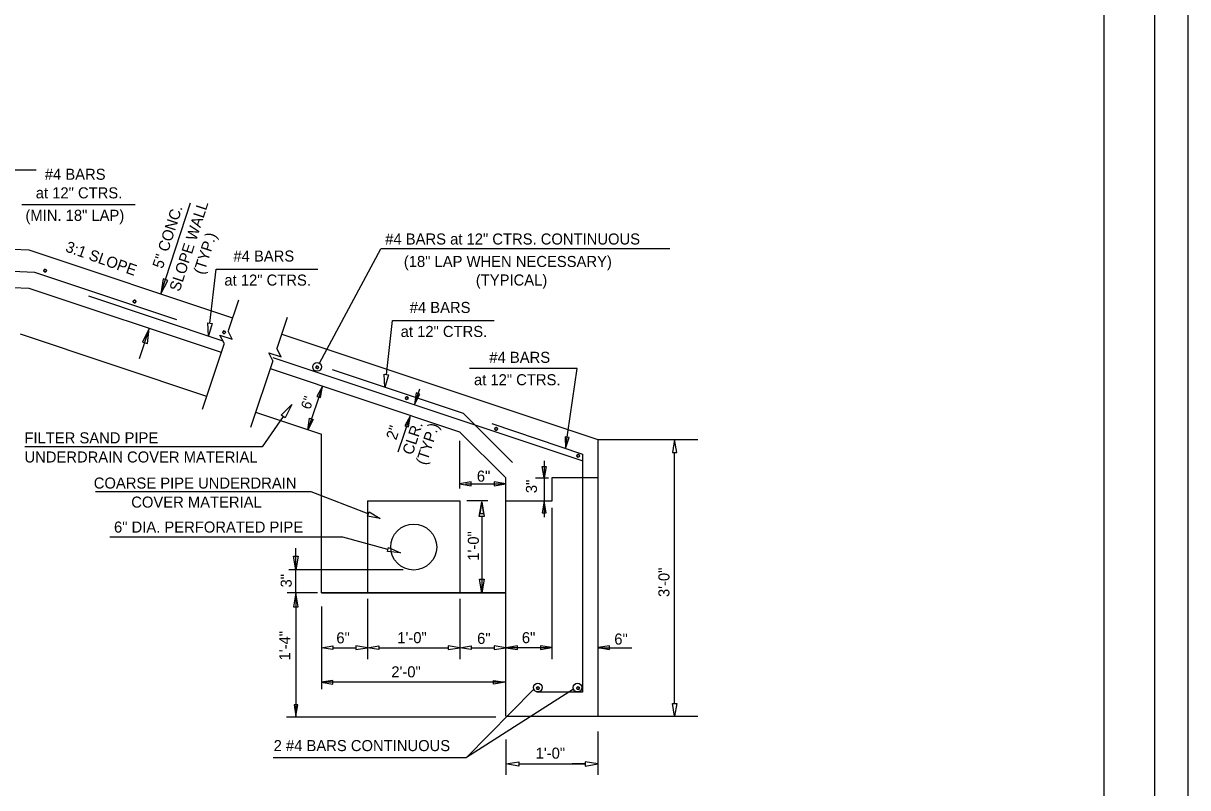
# Model space of a CAD drawing. Extents: x 570 to 2152770, y 726 to 139926.
# Drawn here: x 2151662.08 to 2151674.73, y 139329.09 to 139337.39 of the extents above; entities that cross this region are included whole.
import ezdxf

# ---------------------------------------------------------------- set-up
doc = ezdxf.new("R2010")
doc.units = 0
for name, color, linetype in [('4', 7, 'Continuous'), ('7', 7, 'Continuous'), ('9', 7, 'Continuous'), ('Default', 7, 'Continuous'), ('PR_Dimensions', 7, 'Continuous'), ('PR_Reinforcing', 7, 'Continuous'), ('PR_SlopeWall', 7, 'Continuous'), ('SHT_Plot_Shape_Full', 7, 'Continuous'), ('SHT_Plot_Shape_Half', 7, 'Continuous'), ('SHT_Sheet_Border', 7, 'Continuous'), ('T', 7, 'Continuous'), ('WEEPHOLES', 7, 'Continuous')]:
    doc.layers.add(name, color=color, linetype=linetype)

# ---------------------------------------------------------------- blocks, each defined once
blk = doc.blocks.new('DWG01008_7')
at = {"layer": 'Default'}
for p, q in [((-0.0132, 0), (0, 0.0132)), ((0, 0.0132), (0, -0.0132)), ((0, -0.0132), (0.0132, 0))]:
    blk.add_line(p, q, dxfattribs=at)
blk = doc.blocks.new('ARROWHD_15')
at = {"layer": 'Default'}
blk.add_lwpolyline([(0.0261, -0.0045), (0.0261, 0.0043), (-0.0004, -0.0001)], close=True, dxfattribs=at)

msp = doc.modelspace()

# ---------------------------------------------------------------- linework, layer by layer
at = {"layer": '4'}
for p, q in [((2151668.321, 139332.455), (2151667.821, 139332.455)), ((2151667.821, 139332.455), (2151667.821, 139332.203)), ((2151667.821, 139332.203), (2151667.321, 139332.203))]:
    msp.add_line(p, q, dxfattribs=at)
at = {"layer": '7'}
for p, q in [((2151662.047, 139334.02), (2151664.07, 139333.345)), ((2151664.603, 139333.168), (2151665.32, 139332.929)), ((2151665.32, 139331.206), (2151665.32, 139332.929)), ((2151665.32, 139331.206), (2151667.32, 139331.206))]:
    msp.add_line(p, q, dxfattribs=at)
at = {"layer": '9'}
for start, end in [(159.6694, 339.6694), (339.6694, 159.6694)]:
    msp.add_arc((2151664.26, 139334.037), 0.0143, start, end, dxfattribs=at)
at = {"layer": 'Defpoints'}
for p, q in [((2151668.321, 139332.872), (2151669.408, 139332.872)), ((2151668.321, 139329.867), (2151669.408, 139329.867))]:
    msp.add_line(p, q, dxfattribs=at)
at = {"layer": 'PR_Dimensions'}
for p, q in [((2151662.219, 139335.799), (2151660.003, 139335.799)), ((2151662.064, 139335.426), (2151663.295, 139335.426)), ((2151663.573, 139334.455), (2151663.896, 139335.442)), ((2151669.103, 139334.942), (2151665.962, 139334.942)), ((2151664.174, 139334.723), (2151665.278, 139334.723)), ((2151664.417, 139334.387), (2151664.305, 139334.051)), ((2151664.946, 139334.196), (2151664.834, 139333.86)), ((2151666.09, 139334.165), (2151667.194, 139334.165)), ((2151663.342, 139333.753), (2151663.446, 139334.07)), ((2151664.261, 139333.917), (2151664.022, 139333.2)), ((2151664.789, 139333.726), (2151664.548, 139333.002)), ((2151668.097, 139333.644), (2151666.927, 139333.644)), ((2151667.969, 139332.775), (2151668.097, 139333.644)), ((2151665.328, 139333.453), (2151665.17, 139332.978)), ((2151666.336, 139333.275), (2151666.385, 139333.423)), ((2151666.153, 139332.738), (2151666.286, 139333.134)), ((2151666.816, 139332.859), (2151666.816, 139332.34)), ((2151668.36, 139332.872), (2151669.274, 139332.872)), ((2151669.154, 139330.007), (2151669.154, 139332.732)), ((2151667.737, 139332.642), (2151667.737, 139332.203)), ((2151667.644, 139332.456), (2151667.784, 139332.456)), ((2151666.882, 139332.391), (2151667.317, 139332.391)), ((2151665.208, 139332.303), (2151662.863, 139332.303)), ((2151667.124, 139332.207), (2151666.899, 139332.207)), ((2151667.737, 139332.203), (2151667.737, 139332.028)), ((2151667.82, 139332.13), (2151667.82, 139330.487)), ((2151665.549, 139331.811), (2151663.02, 139331.811)), ((2151665.041, 139331.206), (2151665.041, 139331.692)), ((2151666.204, 139331.456), (2151664.965, 139331.456)), ((2151665.274, 139331.206), (2151664.946, 139331.206)), ((2151665.27, 139331.206), (2151664.992, 139331.206)), ((2151665.041, 139331.206), (2151665.041, 139329.868)), ((2151667.32, 139331.206), (2151665.32, 139331.206)), ((2151665.317, 139331.061), (2151665.317, 139330.162)), ((2151665.818, 139331.143), (2151665.818, 139330.486)), ((2151666.82, 139331.143), (2151666.82, 139330.486)), ((2151665.442, 139330.611), (2151665.693, 139330.611)), ((2151665.943, 139330.611), (2151666.694, 139330.611)), ((2151666.945, 139330.611), (2151667.195, 139330.611)), ((2151667.82, 139330.612), (2151667.32, 139330.612)), ((2151668.32, 139330.612), (2151668.689, 139330.612)), ((2151667.32, 139330.237), (2151665.317, 139330.237)), ((2151664.938, 139329.862), (2151667.213, 139329.862)), ((2151668.441, 139329.867), (2151669.274, 139329.867)), ((2151668.321, 139329.701), (2151668.321, 139329.23)), ((2151667.321, 139329.615), (2151667.321, 139329.23)), ((2151664.793, 139329.421), (2151666.894, 139329.421)), ((2151667.461, 139329.35), (2151668.181, 139329.35)), ((2151668.181, 139329.35), (2151668.041, 139329.35))]:
    msp.add_line(p, q, dxfattribs=at)
for points in [[(2151665.298, 139333.7), (2151665.962, 139334.942)], [(2151664.107, 139334.136), (2151664.174, 139334.723)], [(2151666.023, 139333.578), (2151666.09, 139334.165)], [(2151664.903, 139333.123), (2151664.673, 139332.794), (2151662.095, 139332.794)], [(2151665.826, 139332.064), (2151665.208, 139332.303)], [(2151667.06, 139332.036), (2151667.06, 139331.206)], [(2151666.04, 139331.679), (2151665.549, 139331.811)], [(2151668.056, 139330.16), (2151666.894, 139329.421)], [(2151667.623, 139330.159), (2151666.894, 139329.421)]]:
    msp.add_lwpolyline(points, dxfattribs=at)
for points in [[(2151664.13, 139334.133), (2151664.091, 139333.997), (2151664.084, 139334.139)], [(2151666.046, 139333.575), (2151666.007, 139333.439), (2151665.999, 139333.581)], [(2151665.269, 139333.341), (2151665.308, 139333.328), (2151665.328, 139333.453)], [(2151664.881, 139333.138), (2151664.995, 139333.254), (2151664.925, 139333.108)], [(2151665.19, 139333.103), (2151665.229, 139333.09), (2151665.17, 139332.978)], [(2151669.131, 139332.732), (2151669.178, 139332.732), (2151669.154, 139332.872)], [(2151667.716, 139332.581), (2151667.758, 139332.581), (2151667.737, 139332.456)], [(2151667.033, 139332.036), (2151667.06, 139332.196), (2151667.087, 139332.036)], [(2151667.039, 139332.071), (2151667.081, 139332.071), (2151667.06, 139332.196)], [(2151667.716, 139332.078), (2151667.758, 139332.078), (2151667.737, 139332.203)], [(2151665.835, 139332.086), (2151665.957, 139332.014), (2151665.818, 139332.042)], [(2151666.046, 139331.701), (2151666.175, 139331.642), (2151666.034, 139331.656)], [(2151665.016, 139331.606), (2151665.066, 139331.606), (2151665.041, 139331.456)], [(2151667.035, 139331.356), (2151667.085, 139331.356), (2151667.06, 139331.206)], [(2151665.016, 139331.055), (2151665.066, 139331.055), (2151665.041, 139331.206)], [(2151665.442, 139330.632), (2151665.442, 139330.591), (2151665.317, 139330.611)], [(2151665.693, 139330.632), (2151665.693, 139330.591), (2151665.818, 139330.611)], [(2151665.943, 139330.632), (2151665.943, 139330.591), (2151665.818, 139330.611)], [(2151666.694, 139330.632), (2151666.694, 139330.591), (2151666.82, 139330.611)], [(2151666.945, 139330.632), (2151666.945, 139330.591), (2151666.82, 139330.611)], [(2151667.195, 139330.632), (2151667.195, 139330.591), (2151667.32, 139330.611)], [(2151665.062, 139329.993), (2151665.02, 139329.993), (2151665.041, 139329.868)], [(2151669.131, 139330.007), (2151669.178, 139330.007), (2151669.154, 139329.867)], [(2151667.461, 139329.374), (2151667.461, 139329.327), (2151667.321, 139329.35)], [(2151668.181, 139329.374), (2151668.181, 139329.327), (2151668.321, 139329.35)]]:
    msp.add_lwpolyline(points, close=True, dxfattribs=at)
for centre in [(2151665.271, 139333.661), (2151667.668, 139330.179), (2151668.099, 139330.179)]:
    msp.add_circle(centre, 0.0479, dxfattribs=at)
at = {"layer": 'PR_Reinforcing'}
for p, q in [((2151659.233, 139334.813), (2151662.202, 139334.691)), ((2151662.202, 139334.691), (2151663.744, 139334.177)), ((2151662.787, 139334.432), (2151664.246, 139333.945)), ((2151664.789, 139333.765), (2151668.147, 139332.645)), ((2151666.862, 139333.154), (2151665.439, 139333.628)), ((2151666.862, 139333.154), (2151667.392, 139332.624)), ((2151667.168, 139333.047), (2151668.154, 139332.714)), ((2151668.154, 139332.714), (2151668.154, 139330.13)), ((2151668.154, 139330.13), (2151667.654, 139330.13))]:
    msp.add_line(p, q, dxfattribs=at)
for centre in [(2151662.317, 139334.706), (2151663.288, 139334.371), (2151664.26, 139334.036), (2151665.273, 139333.657), (2151666.244, 139333.322), (2151667.216, 139332.988), (2151668.105, 139332.696), (2151667.67, 139330.172), (2151668.105, 139330.172)]:
    msp.add_circle(centre, 0.0143, dxfattribs=at)
for centre, start, end in [((2151662.317, 139334.706), 159.6694, 339.6694), ((2151662.317, 139334.706), 339.6694, 159.6694), ((2151663.288, 139334.371), 159.6694, 339.6694), ((2151663.288, 139334.371), 339.6694, 159.6694), ((2151665.272, 139333.657), 159.6694, 339.6694), ((2151665.272, 139333.657), 339.6694, 159.6694), ((2151666.244, 139333.322), 339.6694, 159.6694), ((2151666.244, 139333.322), 159.6694, 339.6694), ((2151667.216, 139332.988), 159.6694, 339.6694), ((2151667.216, 139332.988), 339.6694, 159.6694), ((2151668.106, 139332.696), 159.6694, 339.6694), ((2151668.106, 139332.696), 339.6694, 159.6694), ((2151667.67, 139330.172), 1.9719, 181.9719), ((2151667.67, 139330.172), 181.9719, 1.9719), ((2151668.105, 139330.172), 1.9719, 181.9719), ((2151668.105, 139330.172), 181.9719, 1.9719)]:
    msp.add_arc(centre, 0.0143, start, end, dxfattribs=at)
at = {"layer": 'PR_SlopeWall'}
for p, q in [((2151659.138, 139335.058), (2151662.138, 139334.933)), ((2151659.138, 139335.058), (2151662.138, 139334.933)), ((2151662.138, 139334.933), (2151664.353, 139334.195)), ((2151659.125, 139334.641), (2151662.138, 139334.516)), ((2151659.138, 139334.641), (2151662.138, 139334.516)), ((2151662.138, 139334.516), (2151664.228, 139333.82)), ((2151662.138, 139334.516), (2151664.228, 139333.82)), ((2151664.886, 139334.017), (2151668.32, 139332.872)), ((2151664.761, 139333.642), (2151666.816, 139332.957)), ((2151666.816, 139332.957), (2151667.32, 139332.456)), ((2151668.32, 139332.872), (2151668.321, 139329.865)), ((2151667.321, 139329.867), (2151667.32, 139332.456)), ((2151667.321, 139329.867), (2151668.321, 139329.867))]:
    msp.add_line(p, q, dxfattribs=at)
at = {"layer": 'SHT_Plot_Shape_Full'}
msp.add_lwpolyline([(2151638.727, 139342.197), (2151674.727, 139342.197), (2151674.727, 139318.197), (2151638.727, 139318.197)], close=True, dxfattribs=at)
at = {"layer": 'SHT_Plot_Shape_Half'}
msp.add_lwpolyline([(2151640.365, 139341.372), (2151674.365, 139341.372), (2151674.365, 139319.372), (2151640.365, 139319.372)], close=True, dxfattribs=at)
at = {"layer": 'SHT_Sheet_Border'}
msp.add_lwpolyline([(2151673.815, 139319.872), (2151642.315, 139319.872), (2151642.315, 139340.872), (2151673.815, 139340.872)], close=True, dxfattribs=at)
at = {"layer": 'T'}
msp.add_circle((2151666.32, 139331.705), 0.25, dxfattribs=at)
at = {"layer": 'WEEPHOLES'}
for p, q in [((2151665.82, 139332.205), (2151665.82, 139331.206)), ((2151665.82, 139332.205), (2151666.82, 139332.205)), ((2151666.82, 139332.205), (2151666.82, 139331.206)), ((2151665.82, 139331.206), (2151666.82, 139331.206))]:
    msp.add_line(p, q, dxfattribs=at)

# ---------------------------------------------------------------- block references
at = {"layer": 'PR_Dimensions'}
for name, p, xscale, yscale, rotation in [('ARROWHD_15', (2151663.574, 139334.457), 6.151530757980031, 6.151530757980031, 71.85226335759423), ('ARROWHD_15', (2151663.448, 139334.077), 6.151530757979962, 6.151530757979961, -106.5417947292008), ('DWG01008_7', (2151664.283, 139333.984), 5.344315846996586, 5.344315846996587, 71.56518708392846), ('DWG01008_7', (2151664.812, 139333.793), 5.344315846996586, 5.344315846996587, 71.56518708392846), ('ARROWHD_15', (2151666.328, 139333.255), 4.724399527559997, 4.724399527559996, 71.25269404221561), ('ARROWHD_15', (2151666.285, 139333.132), 4.724399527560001, 4.72439952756, -108.77447516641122), ('ARROWHD_15', (2151667.969, 139332.777), 4.724399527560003, 4.724399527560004, 81.62001236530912), ('ARROWHD_15', (2151667.319, 139332.391), 4.7243995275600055, 4.7243995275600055, 180), ('ARROWHD_15', (2151667.819, 139330.612), 4.7243995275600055, 4.7243995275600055, 180), ('ARROWHD_15', (2151667.312, 139330.237), 4.731946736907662, -4.731946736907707, 180)]:
    msp.add_blockref(name, p, dxfattribs=dict(at, xscale=xscale, yscale=yscale, rotation=rotation))
for p, xscale, yscale in [((2151666.82, 139332.391), 4.7243995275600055, 4.7243995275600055), ((2151667.324, 139330.612), 4.7243995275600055, 4.7243995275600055), ((2151668.325, 139330.613), 4.7243995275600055, 4.7243995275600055), ((2151665.317, 139330.237), 4.731946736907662, 4.731946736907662)]:
    msp.add_blockref('ARROWHD_15', p, dxfattribs=dict(at, xscale=xscale, yscale=yscale))

# ---------------------------------------------------------------- texts
at = {"layer": 'T'}
for s, p in [('#4 BARS', (2151662.313, 139335.693)), ('at 12" CTRS.', (2151662.215, 139335.491)), ('(MIN. 18" LAP)', (2151662.103, 139335.247)), ('#4 BARS at 12" CTRS. CONTINUOUS', (2151666.011, 139334.99)), ('#4 BARS', (2151664.362, 139334.805)), ('(18" LAP WHEN NECESSARY)', (2151666.213, 139334.746)), ('at 12" CTRS.', (2151664.264, 139334.544)), ('(TYPICAL)', (2151666.995, 139334.545)), ('#4 BARS', (2151666.277, 139334.247)), ('at 12" CTRS.', (2151666.179, 139333.986)), ('#4 BARS', (2151667.142, 139333.705)), ('at 12" CTRS.', (2151666.975, 139333.462)), ('FILTER SAND PIPE', (2151662.092, 139332.831)), ('UNDERDRAIN COVER MATERIAL', (2151662.092, 139332.623)), ('COARSE PIPE UNDERDRAIN', (2151662.845, 139332.34)), ('6"', (2151667.006, 139332.415)), ('COVER MATERIAL', (2151663.252, 139332.133)), ('6" DIA. PERFORATED PIPE', (2151663.065, 139331.862)), ('6"', (2151665.48, 139330.659)), ('1\'-0"', (2151666.142, 139330.661)), ('6"', (2151667.009, 139330.653)), ('6"', (2151667.495, 139330.661)), ('6"', (2151668.499, 139330.646)), ('2\'-0"', (2151666.077, 139330.29)), ('2 #4 BARS CONTINUOUS', (2151664.799, 139329.489)), ('1\'-0"', (2151667.645, 139329.407))]:
    msp.add_text(s, height=0.12, dxfattribs=at).set_placement(p)
for s, height, rotation, p in [('5" CONC. ', 0.12, 71.9826, (2151663.593, 139334.721)), ('SLOPE WALL', 0.12, 71.9826, (2151663.777, 139334.471)), ('(TYP.)', 0.12, 71.9826, (2151664.038, 139334.656)), ('3:1 SLOPE', 0.12, 340.4558, (2151662.529, 139334.917)), ('6"', 0.1102, 70.4717, (2151665.194, 139333.191)), ('2"', 0.12, 71.6994, (2151666.13, 139332.86)), ('CLR.', 0.12, 71.6994, (2151666.307, 139332.697)), ('(TYP.)', 0.12, 71.6994, (2151666.454, 139332.588)), ('3"', 0.12, 90, (2151667.659, 139332.29)), ('1\'-0"', 0.12, 90, (2151667.028, 139331.557)), ('3\'-0"', 0.12, 90, (2151669.098, 139331.162)), ('3"', 0.12, 90, (2151664.995, 139331.266)), ('1\'-4"', 0.12, 90, (2151664.979, 139330.474))]:
    msp.add_text(s, height=height, rotation=rotation, dxfattribs=at).set_placement(p)

doc.saveas('drawing.dxf')
